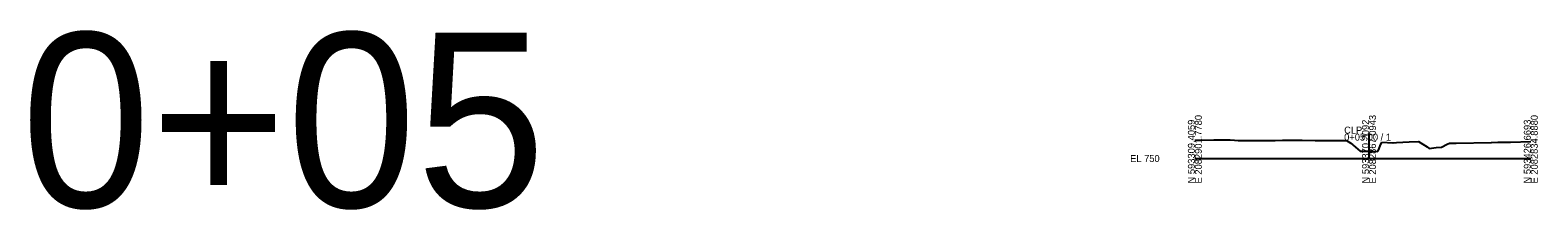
# Model space of a CAD drawing. Extents: x -577 to 1138, y -35 to 4556.
# Drawn here: x -468 to 138, y 479 to 551 of the extents above; entities that cross this region are included whole.
import ezdxf

# ---------------------------------------------------------------- set-up
doc = ezdxf.new("R2010")
doc.units = 0
for name, color, linetype in [('GK_Cells', 7, 'Continuous'), ('SC_Scratch1', 7, 'Continuous'), ('XS_X_Ground_Line', 7, 'Continuous')]:
    doc.layers.add(name, color=color, linetype=linetype)

msp = doc.modelspace()

# ---------------------------------------------------------------- linework, layer by layer
at = {"layer": 'GK_Cells'}
for p, q in [((70, 500), (70, 510)), ((0, 500), (70, 500)), ((70, 500), (135, 500))]:
    msp.add_line(p, q, dxfattribs=at)
at = {"layer": 'XS_X_Ground_Line'}
for p, q in [((0, 507.4), (2.7, 507.35)), ((2.7, 507.35), (7.63, 507.45)), ((7.63, 507.45), (13.77, 507.47)), ((13.77, 507.47), (14.15, 507.48)), ((14.15, 507.48), (15.94, 507.32)), ((15.94, 507.32), (17.41, 507.3)), ((17.41, 507.3), (23.03, 507.25)), ((23.03, 507.25), (23.93, 507.25)), ((23.93, 507.25), (26.6, 507.27)), ((26.6, 507.27), (27.52, 507.28)), ((27.52, 507.28), (29.67, 507.29)), ((29.67, 507.29), (31.07, 507.3)), ((31.07, 507.3), (32.31, 507.29)), ((32.31, 507.29), (35.21, 507.31)), ((35.21, 507.31), (38.63, 507.32)), ((38.63, 507.32), (40.04, 507.33)), ((40.04, 507.33), (43.08, 507.31)), ((43.08, 507.31), (48.3, 507.28)), ((48.3, 507.28), (50.89, 507.26)), ((50.89, 507.26), (52.11, 507.26)), ((52.11, 507.26), (55.03, 507.24)), ((55.03, 507.24), (56.85, 507.23)), ((56.85, 507.23), (61, 507.26)), ((61, 507.26), (62.65, 506.14)), ((62.65, 506.14), (62.83, 506)), ((62.83, 506), (63.3, 505.61)), ((63.3, 505.61), (63.57, 505.39)), ((63.57, 505.39), (66.48, 502.99)), ((66.48, 502.99), (67.25, 502.99)), ((67.25, 502.99), (71.09, 502.94)), ((71.09, 502.94), (73.53, 502.78)), ((73.53, 502.78), (74.04, 504.04)), ((74.04, 504.04), (74.48, 505.12)), ((74.48, 505.12), (75.08, 506.59)), ((75.08, 506.59), (79.6, 506.37)), ((79.6, 506.37), (79.7, 506.37)), ((79.7, 506.37), (81.02, 506.43)), ((81.02, 506.43), (86.18, 506.66)), ((86.18, 506.66), (89.73, 506.81)), ((89.73, 506.81), (89.87, 506.82)), ((89.87, 506.82), (93.35, 504.64)), ((93.35, 504.64), (94.19, 504.08)), ((94.19, 504.08), (97.04, 504.37)), ((97.04, 504.37), (99.11, 504.59)), ((99.11, 504.59), (101.36, 505.71)), ((101.36, 505.71), (102.39, 506.14)), ((102.39, 506.14), (103.47, 506.15)), ((103.47, 506.15), (103.72, 506.15)), ((103.72, 506.15), (104.34, 506.16)), ((104.34, 506.16), (104.96, 506.17)), ((104.96, 506.17), (119.03, 506.5)), ((119.03, 506.5), (119.17, 506.5)), ((119.17, 506.5), (121.77, 506.53)), ((121.77, 506.53), (122.44, 506.54)), ((122.44, 506.54), (124.52, 506.57)), ((124.52, 506.57), (125.4, 506.58)), ((125.4, 506.58), (125.75, 506.58)), ((125.75, 506.58), (126.19, 506.59)), ((126.19, 506.59), (126.91, 506.6)), ((126.91, 506.6), (135, 506.82))]:
    msp.add_line(p, q, dxfattribs=at)

# ---------------------------------------------------------------- texts
at = {"layer": 'GK_Cells'}
for s, p in [('N 593309.4059', (0, 490)), ('E 2082901.7780', (2.8, 490)), ('N 593370.2092', (70, 490)), ('E 2082867.0943', (72.8, 490)), ('N 593426.6693', (135, 490)), ('E 2082834.8880', (137.8, 490))]:
    msp.add_text(s, height=2.8, rotation=90, dxfattribs=at).set_placement(p)
for s, p in [('0+05.00 / 1', (60, 507.2)), ('CLP_', (60, 510)), ('EL 750', (-26, 498.6))]:
    msp.add_text(s, height=2.8, dxfattribs=at).set_placement(p)
at = {"layer": 'SC_Scratch1'}
msp.add_text('0+05', height=70, dxfattribs=at).set_placement((-471.72, 480.44))

doc.saveas('drawing.dxf')
